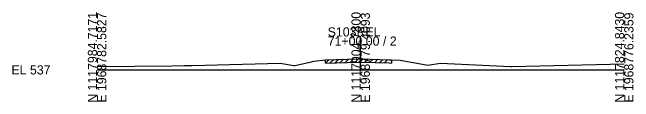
# Model space of a CAD drawing. Extents: x -26 to 163, y -10 to 24518.
# Drawn here: x -25.7 to 162.8, y 19490.3 to 19517.5 of the extents above; entities that cross this region are included whole.
import ezdxf

# ---------------------------------------------------------------- set-up
doc = ezdxf.new("R2010")
doc.units = 0
for name, color, linetype in [('RD_GPK_XS_Cell', 7, 'Continuous'), ('RD_XS_ExGround', 7, 'Continuous'), ('RD_XS_ExPaveRet', 7, 'Continuous'), ('RD_XS_TX_Elev_EX', 7, 'Continuous')]:
    doc.layers.add(name, color=color, linetype=linetype)

msp = doc.modelspace()

# ---------------------------------------------------------------- linework, layer by layer
at = {"layer": 'RD_GPK_XS_Cell'}
for p, q in [((80, 19500), (80, 19510.18)), ((0, 19500), (80, 19500)), ((80, 19500), (160, 19500))]:
    msp.add_line(p, q, dxfattribs=at)
at = {"layer": 'RD_XS_ExGround'}
msp.add_lwpolyline([(0, 19501), (22.71, 19501.22), (26.54, 19501.29), (28.9, 19501.35), (55.55, 19502.09), (59.7, 19501.38), (60.06, 19501.32), (65.04, 19502.5), (65.42, 19502.6), (65.75, 19502.64), (69.29, 19503.06), (79.31, 19503.37), (80.18, 19503.39), (88.69, 19503.1), (89.32, 19503.08), (92.02, 19502.98), (99.92, 19501.49), (100.29, 19501.42), (104.23, 19502.05), (125.47, 19501.05), (125.84, 19501.04), (160, 19501.85)], dxfattribs=at)
at = {"layer": 'RD_XS_ExPaveRet'}
for p, q in [((69.29, 19502.06), (70.32, 19503.1)), ((69.29, 19502.06), (69.29, 19503.06)), ((69.29, 19502.06), (79.31, 19502.37)), ((70.79, 19502.11), (71.82, 19503.14)), ((72.29, 19502.16), (73.32, 19503.19)), ((73.79, 19502.2), (74.82, 19503.23)), ((75.29, 19502.25), (76.32, 19503.28)), ((76.79, 19502.29), (77.82, 19503.32)), ((78.29, 19502.34), (79.32, 19503.37)), ((79.31, 19502.37), (80.18, 19502.39)), ((79.79, 19502.38), (80.78, 19503.37)), ((80.18, 19502.39), (88.69, 19502.1)), ((81.29, 19502.36), (82.26, 19503.32)), ((82.79, 19502.3), (83.76, 19503.27)), ((84.29, 19502.25), (85.26, 19503.22)), ((85.79, 19502.2), (86.76, 19503.17)), ((87.29, 19502.15), (88.26, 19503.12)), ((88.69, 19502.1), (89.32, 19502.08)), ((89.32, 19503.08), (89.32, 19502.08))]:
    msp.add_line(p, q, dxfattribs=at)

# ---------------------------------------------------------------- texts
at = {"layer": 'RD_GPK_XS_Cell'}
for s, p in [('N 1117984.7171', (0, 19490)), ('E 1968782.5827', (2.8, 19490)), ('N 1117904.7800', (80, 19490)), ('E 1968779.4093', (82.8, 19490)), ('N 1117824.8430', (160, 19490)), ('E 1968776.2359', (162.8, 19490))]:
    msp.add_text(s, height=2.8, rotation=90, dxfattribs=at).set_placement(p)
for s, p in [('S103REL', (70, 19510.18)), ('71+00.00 / 2', (70, 19507.38)), ('EL 537', (-26, 19498.6))]:
    msp.add_text(s, height=2.8, dxfattribs=at).set_placement(p)
at = {"layer": 'RD_XS_TX_Elev_EX'}
msp.add_text('540.39', height=0.8, rotation=90, dxfattribs=at).set_placement((79.9, 19505.39))

doc.saveas('drawing.dxf')
